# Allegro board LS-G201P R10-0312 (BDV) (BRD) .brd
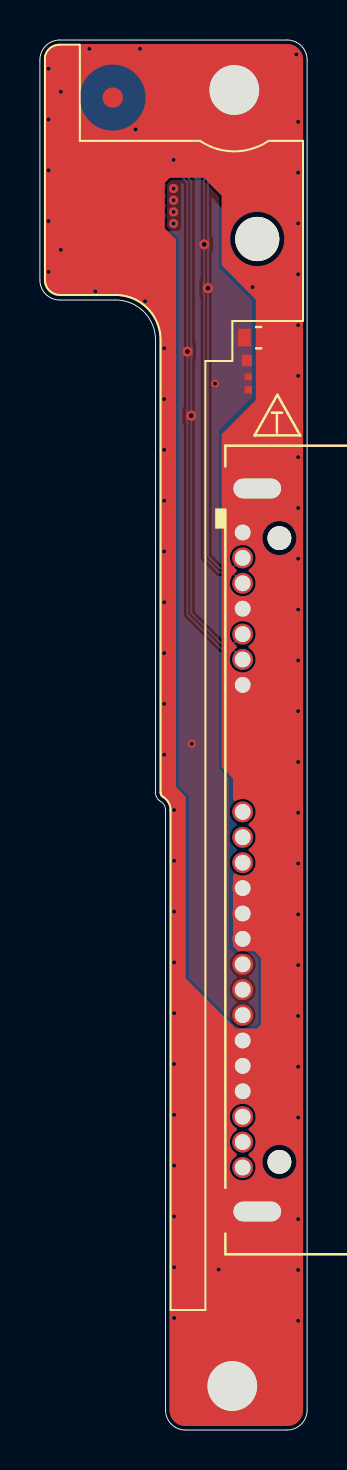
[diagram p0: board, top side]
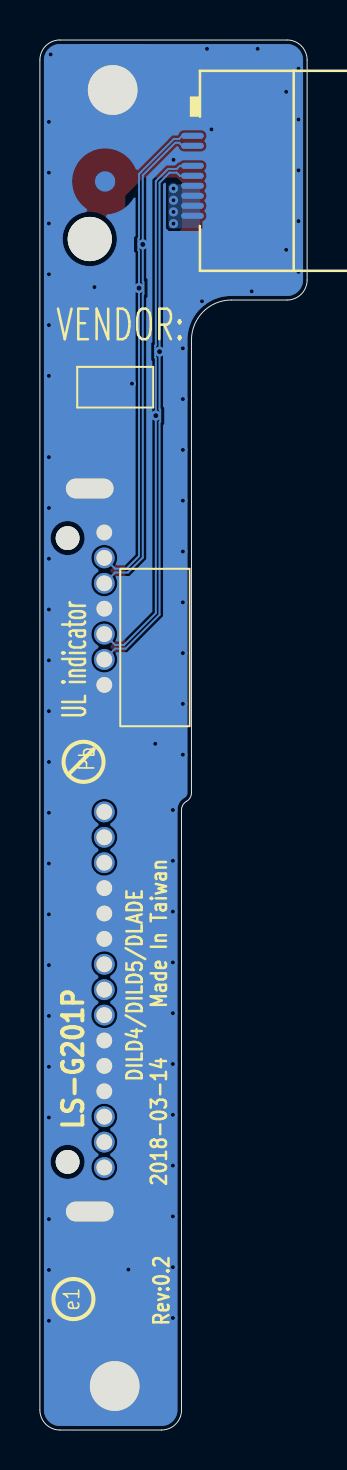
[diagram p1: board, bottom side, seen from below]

Outline 13.4 x 69.5 mm; copper layers: TOP, GND1, GND2, BOTTOM. Coordinates in mm from the lower left corner of the outline.
Outline path: 0,68.5 0,57.5 arc(0.29,56.79) 1,56.5 3.8,56.5 arc(5.21,55.91) 5.8,54.5 5.8,31.87 arc(5.87,31.62) 6.05,31.43 arc(6.23,31.25) 6.3,31 6.3,1 arc(6.59,0.29) 7.3,0 12.4,0 arc(13.11,0.29) 13.4,1 13.4,68.5 arc(13.11,69.21) 12.4,69.5 1,69.5 arc(0.29,69.21) 0,68.5

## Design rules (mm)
net group SATA_PRX_C_DTX_0: nets SATA_PRX_C_DTX_N0 SATA_PRX_C_DTX_P0
net group SATA_PTX_C_DRX_0: nets SATA_PTX_C_DRX_N0 SATA_PTX_C_DRX_P0
nets with their own width: min track width 0.508; nets GND
nets with their own width: min track width 2.032; nets +5V_HDD

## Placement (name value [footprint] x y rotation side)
C232  0.1U_0201_10V K X5R  [C_0201]  10.45 52.65 0 top
C237  1000P_0402_50V7K  [C_0402]  10.38 53.47 0 top
C238  10U_0603_6.3V6M  [C_0603]  10.26 54.62 0 top
C239  0.1U_0201_10V K X5R  [C_0201]  10.45 52.01 0 top
FD1  CF  [FIDUCIAL_C40M80]  3.65 66.62 0 top
FD2  CF  [FIDUCIAL_C40M80]  10.13 62.43 180 bottom
H1  HOLEA  [H_2P5]  9.75 67 0 top
H2  HOLEA  [H_2P5]  9.65 2.2 0 top
H3  HOLEA  [H_2P2N]  10.9 59.55 0 top
JHDD1  ACES_51530-01001-P01  [ACES_51530-01001-P01_10P]  5.75 65.21 90 bottom
JHDD2  SDAN_603008-022041  [SDAN_603008-022041_22P]  10.17 44.88 90 top
NOREF  -  []  9.65 2.2 0 top
NOREF#2  -  []  10.76 49.73 0 top
NOREF#3  -  []  -70.39 53.94 0 top
NOREF#4  -  []  9.75 67 0 top
NOREF#5  -  []  -12.86 -55.05 0 top
NOREF#6  -  []  33.62 51.89 180 bottom
NOREF#7  -  []  7.02 8.45 90 bottom
NOREF#8  -  []  9.56 30.23 90 bottom

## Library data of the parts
C232 C239 = C_0201
C237 = C_0402
C238 = C_0603
FD1 FD2 = FIDUCIAL_C40M80
H1 H2 = H_2P5
H3 = H_2P2N
JHDD1 = ACES_51530-01001-P01_10P
JHDD2 = SDAN_603008-022041_22P

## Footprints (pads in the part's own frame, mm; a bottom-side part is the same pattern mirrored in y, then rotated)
ACES_51530-01001-P01_10P
  oval 0.305x1.143 smd: 1(0,0) 2(-0.5,0) 3(-1,0) 4(-1.5,0) 5(-2,0) 6(-2.5,0) 7(-3,0) 8(-3.5,0) 9(-4,0) 10(-4.5,0)
  rect 0.787x2.007 smd: 11(1.7,-3.325) 12(-6.2,-3.325)
C_0201
  rect 0.381x0.356 smd: 1(0,0) 2(0.584,0)
C_0402
  rect 0.508x0.584 smd: 1(0,0) 2(0.914,0)
C_0603
  rect 0.635x0.889 smd: 1(0,0) 2(1.397,0)
FIDUCIAL_C40M80
  round 1.016 smd: 1(0,0)
H_2P2N
  round 2.21 hole 2.21 unplated: (0,0)
H_2P5
  round 2.997 hole 2.489: 1(0,0)
SDAN_603008-022041_22P
  round 1.194 hole 1.194 unplated: (-31.47,-1.84) (-0.28,-1.84)
  round 1.041 hole 0.787: 1(0,0) 2(-1.27,0) 3(-2.54,0) 4(-3.81,0) 5(-5.08,0) 6(-6.35,0) 7(-7.62,0) 8(-13.97,0) 9(-15.24,0) 10(-16.51,0) 11(-17.78,0) 12(-19.05,0) 13(-20.32,0) 14(-21.59,0) 15(-22.86,0) 16(-24.13,0) 17(-25.4,0) 18(-26.67,0) 19(-27.94,0) 20(-29.21,0) 21(-30.48,0) 22(-31.75,0)
  oval 1.803x3.2 hole 0.991x2.388: 23(-33.95,-0.73) 24(2.2,-0.73)

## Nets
+5V_HDD: C232.1 C237.1 C238.1 C239.1 JHDD1.7 JHDD1.8 JHDD1.9 JHDD1.10 JHDD2.14 JHDD2.15 JHDD2.16
GND: C232.2 C237.2 C238.2 C239.2 H1.1(TP-1) H2.1(TP-1) JHDD1.1 JHDD1.4 JHDD1.11 JHDD1.12 JHDD2.1 JHDD2.4 JHDD2.7 JHDD2.11 JHDD2.12 JHDD2.13 JHDD2.17 JHDD2.18 JHDD2.19 JHDD2.23 JHDD2.24
SATA_PRX_C_DTX_N0: JHDD1.5 JHDD2.5
SATA_PRX_C_DTX_P0: JHDD1.6 JHDD2.6
SATA_PTX_C_DRX_N0: JHDD1.3 JHDD2.3
SATA_PTX_C_DRX_P0: JHDD1.2 JHDD2.2

Pads without a net: FD1 1; FD2 1; JHDD2 8 9 10 20 21 22

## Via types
v1: diameter 0.508, hole 0.254, TOP to BOTTOM, 4 vias
v2: diameter 0.457, hole 0.203, TOP to BOTTOM, 61 vias
v3: diameter 0.406, hole 0.203, TOP to BOTTOM, 4 vias

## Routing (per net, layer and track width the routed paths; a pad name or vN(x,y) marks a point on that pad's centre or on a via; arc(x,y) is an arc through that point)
+5V_HDD:
  vias: v2(6.7,62.07) v2(6.7,61.49) v2(6.7,60.9) v2(6.7,60.32) v3(8.78,52.32)
GND: length 198.2
  GND1 w0.203: JHDD2.4 10.87,41.07 ; JHDD2.4 9.62,41.61 ; JHDD2.4 9.47,41.07 ; JHDD2.4 10.71,40.52 ; JHDD2.4 9.62,40.52 ; JHDD2.4 10.71,41.61 ; JHDD2.11 10.87,27.1 ; JHDD2.11 9.47,27.1 ; JHDD2.11 9.62,27.64 ; JHDD2.11 9.62,26.55 ; JHDD2.11 10.71,26.55 ; JHDD2.11 10.71,27.64 ; JHDD2.24 10.9,48.13 ; JHDD2.24 12.65,47.08 ; JHDD2.24 12.65,46.02 ; JHDD2.24 9.15,48.13 ; JHDD2.24 9.15,46.02 ; JHDD2.24 10.9,46.02 ; JHDD2.24 9.15,47.08 ; JHDD2.24 12.65,48.13 ; JHDD2.19 10.87,16.94 ; JHDD2.19 10.71,17.48 ; JHDD2.19 9.62,16.39 ; JHDD2.19 10.71,16.39 ; JHDD2.19 9.47,16.94 ; JHDD2.19 9.62,17.48 ; 10.9,9.87 JHDD2.23 ; JHDD2.23 12.65,9.87 ; JHDD2.23 10.9,11.98 ; JHDD2.23 9.15,10.93 ; JHDD2.23 12.65,11.98 ; JHDD2.23 9.15,9.87 ; JHDD2.23 12.65,10.93 ; JHDD2.23 9.15,11.98 ; JHDD2.17 10.87,19.48 ; JHDD2.17 10.71,18.93 ; JHDD2.17 9.62,20.02 ; JHDD2.17 10.71,20.02 ; JHDD2.17 9.47,19.48 ; JHDD2.17 9.62,18.93 ; 9.47,44.88 JHDD2.1 ; JHDD2.1 9.62,44.33 ; JHDD2.1 10.71,44.33 ; JHDD2.1 10.17,45.57 ; JHDD2.1 9.62,45.42 ; JHDD2.1 10.87,44.88 ; JHDD2.1 10.71,45.42 ; 8.07,67 H1.1 ; H1.1 8.51,65.76 ; H1.1 10.98,65.76 ; H1.1 11.43,67 ; H1.1 10.98,68.24 ; H1.1 9.75,68.68 ; H1.1 8.51,68.24 ; H1.1 9.75,65.32 ; H2.1 9.65,3.88 ; H2.1 11.33,2.2 ; H2.1 10.88,3.44 ; H2.1 8.41,3.44 ; H2.1 7.97,2.2 ; H2.1 8.41,0.96 ; H2.1 10.88,0.96 ; H2.1 9.65,0.52 ; JHDD2.12 10.87,25.83 ; JHDD2.12 9.62,26.37 ; JHDD2.12 9.47,25.83 ; JHDD2.12 10.71,25.28 ; JHDD2.12 9.62,25.28 ; JHDD2.12 10.71,26.37 ; JHDD2.13 10.87,24.56 ; JHDD2.13 9.62,25.1 ; JHDD2.13 10.71,24.01 ; JHDD2.13 9.62,24.01 ; JHDD2.13 10.71,25.1 ; JHDD2.13 9.47,24.56 ; 9.47,37.26 JHDD2.7 ; JHDD2.7 10.71,37.8 ; JHDD2.7 10.71,36.71 ; JHDD2.7 10.17,36.56 ; JHDD2.7 9.62,37.8 ; JHDD2.7 9.62,36.71 ; JHDD2.7 10.87,37.26 ; JHDD2.18 10.87,18.21 ; JHDD2.18 9.62,17.66 ; JHDD2.18 10.71,17.66 ; JHDD2.18 9.62,18.75 ; JHDD2.18 10.71,18.75 ; JHDD2.18 9.47,18.21
  GND2 w0.203: 9.62,25.28 JHDD2.12 ; JHDD2.12 9.47,25.83 ; JHDD2.12 10.71,26.37 ; JHDD2.12 10.87,25.83 ; JHDD2.12 9.62,26.37 ; JHDD2.12 10.71,25.28 ; H1.1 10.98,65.76 ; H1.1 8.51,68.24 ; H1.1 8.51,65.76 ; H1.1 9.75,68.68 ; H1.1 9.75,65.32 ; H1.1 11.43,67 ; H1.1 10.98,68.24 ; H1.1 8.07,67 ; 9.47,27.1 JHDD2.11 ; JHDD2.11 10.87,27.1 ; JHDD2.11 9.62,27.64 ; JHDD2.11 9.62,26.55 ; JHDD2.11 10.71,26.55 ; JHDD2.11 10.71,27.64 ; H2.1 9.65,3.88 ; H2.1 10.88,3.44 ; H2.1 7.97,2.2 ; H2.1 8.41,3.44 ; H2.1 11.33,2.2 ; H2.1 9.65,0.52 ; H2.1 10.88,0.96 ; H2.1 8.41,0.96 ; JHDD2.17 10.71,18.93 ; JHDD2.17 9.47,19.48 ; JHDD2.17 9.62,20.02 ; JHDD2.17 9.62,18.93 ; JHDD2.17 10.71,20.02 ; JHDD2.17 10.87,19.48 ; JHDD2.18 10.87,18.21 ; JHDD2.18 9.62,18.75 ; JHDD2.18 10.71,18.75 ; JHDD2.18 9.62,17.66 ; JHDD2.18 10.71,17.66 ; JHDD2.18 9.47,18.21 ; 9.62,40.52 JHDD2.4 ; JHDD2.4 9.47,41.07 ; JHDD2.4 10.71,41.61 ; JHDD2.4 9.62,41.61 ; JHDD2.4 10.87,41.07 ; JHDD2.4 10.71,40.52 ; 9.62,16.39 JHDD2.19 ; JHDD2.19 9.47,16.94 ; JHDD2.19 10.71,16.39 ; JHDD2.19 9.62,17.48 ; JHDD2.19 10.87,16.94 ; JHDD2.19 10.71,17.48 ; JHDD2.13 10.71,25.1 ; JHDD2.13 9.62,24.01 ; JHDD2.13 10.87,24.56 ; JHDD2.13 9.62,25.1 ; JHDD2.13 10.71,24.01 ; JHDD2.13 9.47,24.56 ; JHDD2.7 10.71,37.8 ; JHDD2.7 10.71,36.71 ; JHDD2.7 10.87,37.26 ; JHDD2.7 9.62,36.71 ; JHDD2.7 9.47,37.26 ; JHDD2.7 9.62,37.8 ; JHDD2.7 10.17,36.56 ; JHDD2.1 10.17,45.57 ; JHDD2.1 10.71,44.33 ; JHDD2.1 9.62,44.33 ; JHDD2.1 10.71,45.42 ; JHDD2.1 10.87,44.88 ; JHDD2.1 9.62,45.42 ; JHDD2.1 9.47,44.88 ; 9.15,9.87 JHDD2.23 ; JHDD2.23 12.65,11.98 ; JHDD2.23 12.65,9.87 ; JHDD2.23 12.65,10.93 ; JHDD2.23 9.15,10.93 ; JHDD2.23 10.9,9.87 ; JHDD2.23 10.9,11.98 ; JHDD2.23 9.15,11.98 ; JHDD2.24 12.65,47.08 ; JHDD2.24 9.15,47.08 ; JHDD2.24 9.15,46.02 ; JHDD2.24 10.9,46.02 ; JHDD2.24 12.65,46.02 ; JHDD2.24 9.15,48.13 ; JHDD2.24 12.65,48.13 ; JHDD2.24 10.9,48.13
  BOTTOM w0.305: v2(4.8,65.03) 4.97,65.21 JHDD1.1 ; 5.82,63.71 6.5,63.71 v2(6.7,63.51)
  BOTTOM w0.508: JHDD1.11 v2(1.05,66.91) ; JHDD1.12 v2(1.05,59.01)
  vias: v2(0.43,68.06) v2(0.43,65.52) v2(0.43,62.98) v2(0.43,60.44) v2(0.43,57.9) v2(2.48,69.06) v2(2.78,56.93) v2(5.02,69.06) v2(5.27,56.44) v2(6.23,54.09) v2(6.23,51.55) v2(6.23,49.01) v2(6.23,46.47) v2(6.23,43.93) v2(6.23,41.39) v2(6.23,38.85) v2(6.23,36.31) v2(6.23,33.77) v2(6.73,31) v2(6.73,28.46) v2(6.73,25.92) v2(6.73,23.38) v2(6.73,20.84) v2(6.73,18.3) v2(6.73,15.76) v2(6.73,13.22) v2(6.73,10.68) v2(6.73,8.14) v2(6.73,5.6) v2(12.86,68.78) v2(12.95,65.41) v2(12.95,62.87) v2(12.95,60.33) v2(12.95,57.79) v2(12.95,55.25) v2(12.95,52.71) v2(12.95,48.64) v2(12.95,46.1) v2(12.95,43.56) v2(12.95,41.02) v2(12.95,38.48) v2(12.95,35.94) v2(12.95,33.4) v2(12.95,30.86) v2(12.95,28.32) v2(12.95,25.78) v2(12.95,23.24) v2(12.95,20.7) v2(12.95,18.16) v2(12.95,15.62) v2(12.95,10.54) v2(12.95,8) v2(12.95,5.46) v3(7.61,34.31) v3(8.96,8.02) v3(10.66,57.14)
SATA_PRX_C_DTX_N0: length 27.2
  BOTTOM w0.097: JHDD2.5 9.63,39.25 9.17,39.25 7.59,40.84 v1(7.59,50.72) 7.59,53.6 7.62,53.63 7.62,54.21 7.59,54.24 7.59,62.44 6.98,63.05 6.54,63.05 6.38,63.21 JHDD1.5
SATA_PRX_C_DTX_P0: length 27.2
  BOTTOM w0.097: JHDD1.6 6.38,62.71 6.54,62.87 6.9,62.87 7.4,62.36 v1(7.4,53.92) 7.4,51.04 7.37,51.01 7.37,50.43 7.4,50.4 7.4,40.76 9.1,39.07 9.63,39.07 JHDD2.6
SATA_PTX_C_DRX_N0: length 24.8
  BOTTOM w0.097: JHDD2.3 9.63,42.88 8.98,42.88 8.24,43.62 8.24,56.77 8.21,56.8 8.21,57.39 8.24,57.42 v1(8.24,59.28) 8.24,62.73 6.61,64.36 6.41,64.36 6.26,64.21 JHDD1.3
SATA_PTX_C_DRX_P0: length 24.8
  BOTTOM w0.097: JHDD1.2 6.26,64.71 6.42,64.55 6.69,64.55 8.43,62.81 8.43,59.6 8.46,59.57 8.46,58.99 8.43,58.95 v1(8.43,57.09) 8.43,43.7 9.06,43.06 9.63,43.06 JHDD2.2

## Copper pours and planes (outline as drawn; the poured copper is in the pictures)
+5V_HDD on TOP: 9.88,20.2 7.46,22.61 7.46,31.69 6.95,32.2 6.95,59.57 6.38,60.14 6.38,62.3 6.57,62.49 8.16,62.49 8.99,61.67 8.99,58.11 10.64,56.46 10.64,51.63 8.99,49.98 8.99,33.09 9.49,32.58 9.49,24.07 9.75,23.82 10.7,23.82 10.95,23.57 10.95,20.33 10.83,20.2
+5V_HDD on BOTTOM: 5.43,62.36 6.83,62.36 6.95,62.24 6.95,60.14 6.89,60.08 5.43,60.08 5.37,60.14 5.37,62.3
GND on TOP (solid shape): outline of 956 points within 0.2,0.2 13.19,69.3
GND on BOTTOM (solid shape): outline of 1292 points within 0.2,0.2 13.19,69.3
GND on GND1, GND2: 7.3,0.2 6.73,0.44 6.5,1 6.5,31 6.41,31.35 6.04,31.72 6,31.87 6,54.5 5.36,56.06 3.8,56.7 1,56.7 0.44,56.94 0.2,57.5 0.2,68.5 0.44,69.06 1,69.3 12.4,69.3 12.96,69.06 13.19,68.5 13.19,1 12.96,0.44 12.4,0.2

Small or netless copper shapes (teardrops, artwork), in the pictures only: 2 on TOP, 3 on BOTTOM

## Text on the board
Ref Des/Silkscreen Bottom: LS-G201P
User.Comments: DLID4/DLID5/DLADE | LS-G201P | 2019-03-14 | 2018-03-14 | QUILL | 1.0
PAGE_OUTLINE: LAYER | NAME | L3 | L2 | L4 | L5 | L1 | L6 | LA-D708P | DUMMY-COOPER | BOT(50 ohm) | GND1 | GND2 | LS-C701P | TOP | BOT(90 ohm) | LS-C703P | VCC | GND | L7 | L9 | L8 | L10 | L11 | L12 | L13 | L14 | LA-XXXXP | LS-XXXXP | LA-D581P | LA-C602P | LA-D751P | IN1(50 ohm) | LS-C706P | IN2(85 ohm) | BOT | LS-D581P | LS-C601P | LS-D751P | IN1 | LS-D701P | TOP(50 ohm) | LS-D582P | LS-C602P | LS-D752P | IN2 | IN2(50,85 ohm) | BOT(50,85 ohm) | LS-D702P | LS-D754P | BOT(85 ohm) | TOP(85 ohm) | LS-C603P | LS-D757P | LS-D758P | TOP(50,85 ohm) | LS-D759P | GND3 | GND4 | LS-D75AP | LS-D75BP | LS-D75CP | LS-D75DP
User.27: GND4
User.28: GND5
User.29: FIGURE | SIZE | 8.0 | 31.0 | 98.0 | 47.0 | 87.0 | 94.0x39.0 | DRILL CHART: TOP to BOTTOM | ALL UNITS ARE IN MILS | TOLERANCE | +3.0/-3.0 | +2.0/-2.0 | PLATED | NON-PLATED | QTY | 61 | 22 | 2 | 1
User.30: HR_1_0mm-6L_171122 | Dummy Copper | L5-GND2 | L6-BOT | 3.8/3.6 | REF | L5
